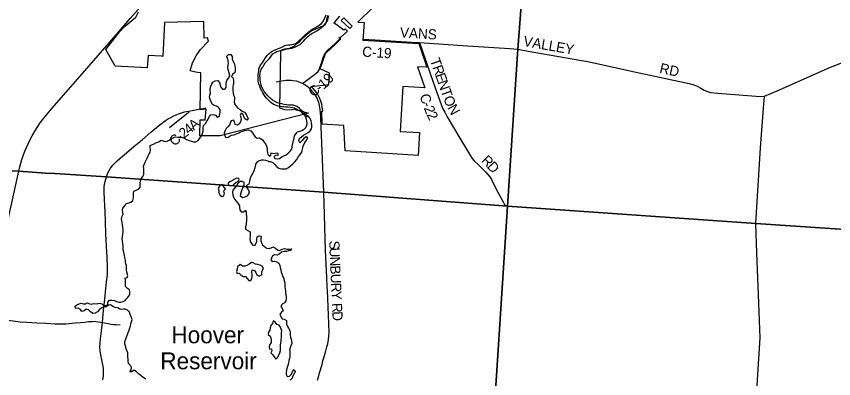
# Model space of a CAD drawing. Extents: x 1674899 to 2057726, y 653888 to 988278.
# Drawn here: x 1855438 to 1879677, y 798397 to 809139 of the extents above; entities that cross this region are included whole.
import ezdxf

# ---------------------------------------------------------------- set-up
doc = ezdxf.new("R2010")
doc.units = 0
for name, color, linetype in [('GM_X_Corporation', 7, 'Continuous'), ('GM_X_County_Road', 7, 'Continuous'), ('GM_X_County_Road_Text', 7, 'Continuous'), ('GM_X_Major_Lake', 7, 'Continuous'), ('GM_X_Major_Lake_Text', 7, 'Continuous'), ('GM_X_Major_River', 7, 'Continuous'), ('GM_X_State_Route', 7, 'Continuous'), ('GM_X_Township', 7, 'Continuous')]:
    doc.layers.add(name, color=color, linetype=linetype)

msp = doc.modelspace()

# ---------------------------------------------------------------- linework, layer by layer
at = {"layer": 'GM_X_Corporation'}
for points in [[(1866027, 809418), (1865570, 808968), (1865749, 808958), (1865718, 808434), (1867372, 808337), (1867616, 807629), (1867336, 807644), (1867551, 807021), (1866904, 807063), (1866822, 805729), (1867392, 805693), (1867351, 805018), (1866597, 805063), (1865185, 805154), (1865155, 805904), (1864509, 805942), (1864501, 806327), (1864526, 806328), (1864512, 806460), (1864496, 806536), (1864471, 806620), (1864437, 806705), (1864397, 806785), (1864365, 806841), (1864301, 806929), (1864242, 806997), (1864212, 807027), (1864179, 807057), (1864703, 807122), (1864724, 807458), (1864445, 807587), (1864609, 808041), (1864644, 808074), (1864880, 808299), (1865062, 808472), (1865032, 808472), (1865006, 808488), (1865043, 808523), (1865057, 808523), (1865255, 808704), (1865245, 808714), (1865194, 808766), (1865155, 808731), (1864852, 808948), (1864871, 808960), (1865028, 809140)], [(1864670, 809164), (1864633, 809031), (1864626, 808978), (1864590, 808873), (1864383, 808793), (1864180, 808703), (1864036, 808584), (1863894, 808456), (1863817, 808362), (1863732, 808311), (1863676, 808251), (1863563, 808196), (1863459, 808169), (1863269, 808119), (1863271, 808069), (1863240, 806424), (1863386, 806382), (1863526, 806367), (1863669, 806383), (1864106, 806273), (1861485, 805600), (1860876, 805597), (1860888, 806070), (1861038, 806073), (1861068, 806389), (1860885, 806368), (1860908, 807463), (1860893, 807463), (1860807, 807478), (1860713, 807490), (1860590, 807519), (1860665, 807762), (1860767, 807971), (1860900, 808159), (1861139, 808401), (1861111, 808506), (1861004, 808492), (1860999, 808987), (1859829, 808961), (1859781, 807951), (1859738, 807954), (1859344, 807980), (1859316, 807611), (1858367, 807661), (1858090, 808159), (1858507, 808685), (1858634, 808831), (1858740, 808916), (1858983, 809113), (1859065, 809276)]]:
    msp.add_lwpolyline(points, dxfattribs=at)
msp.add_lwpolyline([(1865072, 809017), (1865316, 808784), (1865324, 808776), (1865394, 808844), (1865384, 808855), (1865149, 809094)], close=True, dxfattribs=at)
at = {"layer": 'GM_X_County_Road'}
for points in [[(1863927, 807149), (1864283, 807418), (1864334, 807453), (1864387, 807502), (1864414, 807554), (1864439, 807622), (1864484, 807753), (1864542, 807914), (1864570, 807984), (1864606, 808050), (1864642, 808096), (1864687, 808146), (1864789, 808239), (1864902, 808347), (1864988, 808433), (1865037, 808477)], [(1865716, 808463), (1866076, 808441), (1867317, 808363), (1867396, 808359), (1868821, 808266), (1870074, 808188), (1870293, 808165)], [(1867396, 808359), (1867578, 807822), (1867722, 807411), (1867905, 806886), (1867988, 806661), (1868047, 806496), (1868091, 806398), (1868141, 806295), (1868218, 806162), (1868595, 805529), (1868820, 805149), (1868910, 805003), (1868961, 804924), (1869020, 804860), (1869146, 804736), (1869355, 804533), (1869481, 804376), (1869529, 804297), (1869678, 803996), (1869885, 803620), (1869914, 803562), (1869930, 803545)], [(1870293, 808165), (1870309, 808163), (1870615, 808110), (1872380, 807804), (1872796, 807716), (1873633, 807525), (1875394, 807147), (1875535, 807109), (1875625, 807069), (1875741, 807006), (1875837, 806950), (1875938, 806910), (1876028, 806878), (1876232, 806859), (1877504, 806767), (1877627, 806773), (1878001, 806934), (1879588, 807637), (1880629, 808038)], [(1863927, 807149), (1863854, 807181), (1863750, 807215), (1863635, 807231), (1863584, 807238), (1863480, 807241), (1863432, 807239), (1863243, 807210), (1863145, 807190)], [(1864561, 803891), (1864561, 803926), (1864503, 805153), (1864476, 805850), (1864464, 806156), (1864453, 806381), (1864432, 806497), (1864406, 806587), (1864383, 806653), (1864335, 806753), (1864289, 806830), (1864225, 806905), (1864168, 806969), (1864116, 807017), (1864089, 807036), (1863994, 807108), (1863927, 807149)], [(1877369, 802994), (1877508, 805242), (1877600, 806419), (1877627, 806773)], [(1858107, 804378), (1858154, 804496), (1858234, 804633), (1858313, 804738), (1858376, 804801), (1858430, 804854), (1858924, 805276), (1859165, 805478), (1859431, 805702), (1859655, 805890), (1859866, 806052), (1859951, 806106), (1860001, 806134), (1860128, 806199), (1860275, 806259), (1860424, 806303), (1860542, 806330), (1860650, 806352), (1860797, 806382), (1860914, 806399), (1861033, 806421), (1861065, 806429)], [(1860542, 806330), (1860547, 806309), (1860546, 806295), (1860544, 806288), (1860541, 806283), (1860532, 806274), (1860517, 806262), (1860480, 806237), (1860436, 806200), (1859981, 805831)], [(1858004, 798364), (1858012, 798409), (1858022, 798500), (1858025, 798592), (1858022, 798657), (1858018, 798708), (1858012, 798758), (1857995, 798858), (1857972, 798957), (1857933, 799154), (1857922, 799227), (1857914, 799334), (1857933, 799575), (1857961, 799815), (1857988, 800064), (1858027, 800427), (1858061, 800749), (1858095, 801069), (1858116, 801266), (1858139, 801481), (1858144, 801679), (1858131, 802013), (1858124, 802154), (1858116, 802308), (1858103, 802533), (1858096, 802669), (1858083, 803067), (1858070, 803343), (1858061, 803513), (1858050, 803726), (1858044, 803915), (1858041, 804015), (1858044, 804087), (1858051, 804150), (1858068, 804244), (1858087, 804316), (1858107, 804378)], [(1864372, 798348), (1864397, 798443), (1864431, 798566), (1864503, 798820), (1864532, 798925), (1864588, 799118), (1864615, 799218), (1864650, 799343), (1864671, 799432), (1864694, 799556), (1864707, 799664), (1864713, 799761), (1864693, 800283), (1864667, 801023), (1864657, 801114), (1864648, 801383), (1864604, 802208), (1864568, 803602), (1864561, 803891)], [(1869930, 803545), (1869936, 803538), (1870008, 803514), (1877369, 802994)], [(1877332, 796811), (1877420, 798367), (1877499, 799608), (1877454, 800633), (1877398, 802125), (1877369, 802994)], [(1854573, 800349), (1854755, 800266), (1854914, 800205), (1855015, 800169), (1855118, 800145), (1855340, 800109), (1855555, 800083), (1855746, 800073), (1856041, 800054), (1856308, 800043), (1856579, 800027), (1856677, 800021), (1856906, 800027), (1857196, 800056), (1857340, 800059), (1857473, 800073), (1857580, 800087), (1857682, 800095), (1857756, 800098), (1857798, 800096), (1857874, 800083), (1857988, 800064)], [(1857988, 800064), (1858110, 800041), (1858246, 800011), (1858305, 800003), (1858385, 799998), (1858516, 799994)]]:
    msp.add_lwpolyline(points, dxfattribs=at)
at = {"layer": 'GM_X_Major_Lake'}
for p, q in [((1861667, 807947), (1861729, 808005)), ((1864085, 806183), (1864016, 806160))]:
    msp.add_line(p, q, dxfattribs=at)
for points in [[(1861394, 806151), (1861456, 806166), (1861472, 806236), (1861479, 806305), (1861479, 806373), (1861438, 806435), (1861372, 806473), (1861308, 806498), (1861247, 806540), (1861217, 806608), (1861185, 806678), (1861164, 806743), (1861174, 806805), (1861191, 806863), (1861187, 806937), (1861185, 806999), (1861208, 807073), (1861238, 807137), (1861270, 807189), (1861339, 807226), (1861409, 807234), (1861460, 807173), (1861478, 807105), (1861501, 807035), (1861555, 806983), (1861621, 806978), (1861659, 807032), (1861658, 807098), (1861662, 807170), (1861680, 807238), (1861727, 807306), (1861769, 807372), (1861763, 807422), (1861740, 807490), (1861722, 807558), (1861711, 807625), (1861721, 807687), (1861725, 807737), (1861724, 807809), (1861712, 807879), (1861667, 807947)], [(1861729, 808005), (1861801, 808003), (1861837, 807952), (1861842, 807884), (1861860, 807818), (1861901, 807746), (1861921, 807676), (1861932, 807605), (1861932, 807539), (1861916, 807473), (1861853, 807416), (1861815, 807356), (1861865, 807305), (1861880, 807231), (1861876, 807161), (1861867, 807111), (1861857, 807049), (1861863, 806983), (1861862, 806933), (1861868, 806871), (1861881, 806803), (1861911, 806741), (1861905, 806679), (1861900, 806611), (1861910, 806544), (1861961, 806478), (1862005, 806412), (1862071, 806373), (1862132, 806323), (1862200, 806301), (1862250, 806240), (1862279, 806174), (1862313, 806110), (1862274, 806056), (1862217, 806102), (1862187, 806167), (1862168, 806229), (1862108, 806273), (1862072, 806211), (1862099, 806149), (1862105, 806083), (1862090, 806013), (1862050, 805947), (1861996, 805911), (1861930, 805930), (1861916, 805996), (1861875, 806060), (1861805, 806046), (1861781, 805987), (1861766, 805933), (1861714, 805865), (1861662, 805809), (1861623, 805739), (1861599, 805677), (1861614, 805613), (1861654, 805549), (1861724, 805560), (1861776, 805596), (1861826, 805616), (1861892, 805626), (1861964, 805653), (1862036, 805689), (1862088, 805711), (1862153, 805732), (1862211, 805754), (1862261, 805768), (1862327, 805779), (1862394, 805747), (1862442, 805685), (1862476, 805635), (1862523, 805568), (1862577, 805528), (1862653, 805535), (1862724, 805491), (1862782, 805423), (1862824, 805362), (1862857, 805290), (1862879, 805224), (1862880, 805156), (1862884, 805106), (1862901, 805042), (1862955, 804985)], [(1858739, 801474), (1858730, 801499), (1858716, 801559), (1858709, 801629), (1858707, 801681), (1858702, 801745), (1858684, 801805), (1858676, 801861), (1858671, 801913), (1858659, 801988), (1858648, 802046), (1858634, 802098), (1858624, 802148), (1858609, 802212), (1858603, 802280), (1858609, 802334), (1858596, 802406), (1858590, 802476), (1858581, 802544), (1858583, 802611), (1858592, 802681), (1858602, 802741), (1858602, 802811), (1858593, 802885), (1858583, 802953), (1858576, 803013), (1858566, 803083), (1858552, 803133), (1858571, 803199), (1858601, 803271), (1858600, 803321), (1858586, 803387), (1858598, 803455), (1858651, 803525), (1858695, 803591), (1858769, 803610), (1858833, 803634), (1858895, 803682), (1858916, 803754), (1858914, 803820), (1858917, 803888), (1858919, 803952), (1858991, 803986), (1859063, 804013), (1859110, 804077), (1859114, 804139), (1859114, 804205), (1859121, 804265), (1859135, 804331), (1859190, 804387), (1859222, 804453), (1859218, 804523), (1859215, 804577), (1859217, 804627), (1859213, 804699), (1859230, 804751), (1859260, 804811), (1859284, 804871), (1859315, 804939), (1859351, 805005), (1859375, 805058), (1859406, 805112), (1859420, 805174), (1859407, 805255), (1859407, 805307), (1859475, 805344), (1859527, 805364), (1859593, 805394), (1859661, 805423), (1859730, 805463), (1859795, 805447), (1859847, 805430), (1859909, 805436), (1859969, 805464), (1860040, 805517), (1860106, 805549), (1860156, 805563), (1860224, 805560), (1860290, 805554), (1860357, 805550), (1860425, 805525), (1860489, 805489), (1860561, 805461), (1860630, 805442), (1860690, 805422), (1860760, 805421), (1860826, 805461), (1860883, 805529), (1860931, 805595), (1860957, 805661), (1860978, 805733), (1860979, 805839), (1860989, 805907), (1861049, 805960), (1861086, 806030), (1861122, 806094), (1861160, 806162), (1861205, 806218), (1861279, 806232), (1861346, 806207), (1861394, 806151)], [(1863754, 804891), (1863763, 804919), (1863801, 804987), (1863854, 805045), (1863902, 805112), (1863912, 805162), (1863933, 805243), (1863945, 805293), (1863971, 805361), (1864000, 805413), (1864040, 805466), (1864080, 805540), (1864029, 805567), (1863962, 805519), (1863900, 805453), (1863848, 805385), (1863812, 805450), (1863840, 805516), (1863897, 805569), (1863953, 805613), (1864023, 805651), (1864093, 805693), (1864152, 805748), (1864188, 805800), (1864204, 805852), (1864205, 805914), (1864189, 805979), (1864181, 806043), (1864154, 806111), (1864100, 806172), (1864085, 806183)], [(1864016, 806160), (1864030, 806092), (1864041, 806042), (1864051, 805972), (1864045, 805903), (1864026, 805841), (1863958, 805776), (1863908, 805748), (1863840, 805726), (1863769, 805701)], [(1862955, 804985), (1862983, 805019), (1862998, 805091), (1863065, 805071), (1863117, 805079), (1863183, 805088), (1863201, 805026), (1863133, 805012), (1863073, 804979), (1863105, 804926), (1863172, 804916), (1863242, 804924), (1863309, 804977), (1863375, 804999), (1863437, 805037), (1863501, 805078), (1863559, 805138), (1863604, 805202), (1863618, 805268), (1863624, 805336), (1863643, 805406), (1863661, 805470), (1863676, 805532), (1863686, 805594), (1863769, 805701)], [(1862904, 804845), (1862838, 804868), (1862769, 804876), (1862705, 804877), (1862635, 804859), (1862578, 804821), (1862528, 804759), (1862518, 804689), (1862503, 804619), (1862479, 804553), (1862443, 804482), (1862412, 804428), (1862378, 804362), (1862364, 804308), (1862353, 804238), (1862331, 804162), (1862265, 804126), (1862262, 804066), (1862314, 804006), (1862339, 803932), (1862327, 803864), (1862269, 803808), (1862212, 803778), (1862148, 803760), (1862087, 803809), (1862093, 803877), (1862116, 803943), (1862136, 804009), (1862166, 804075), (1862195, 804141), (1862199, 804211), (1862135, 804239), (1862069, 804239), (1862011, 804180), (1861965, 804110), (1861910, 804048), (1861862, 803982), (1861848, 803914), (1861861, 803846), (1861875, 803782), (1861910, 803722), (1861962, 803663), (1862010, 803599), (1862053, 803525), (1862055, 803473), (1862068, 803407), (1862102, 803340), (1862170, 803348), (1862230, 803390), (1862254, 803329), (1862255, 803261), (1862259, 803211), (1862262, 803141), (1862262, 803091), (1862258, 803015), (1862251, 802961), (1862235, 802897), (1862234, 802825), (1862304, 802793), (1862368, 802752), (1862373, 802686), (1862373, 802608), (1862367, 802548), (1862374, 802488), (1862390, 802434), (1862439, 802368), (1862507, 802341), (1862552, 802411), (1862570, 802463), (1862570, 802525), (1862583, 802597), (1862639, 802633), (1862701, 802618), (1862692, 802550), (1862692, 802484), (1862707, 802424), (1862737, 802362), (1862803, 802310), (1862866, 802267), (1862940, 802257), (1862992, 802277), (1863060, 802304), (1863126, 802268), (1863182, 802220), (1863247, 802193), (1863320, 802235), (1863388, 802260), (1863459, 802234), (1863531, 802238), (1863599, 802251), (1863575, 802197), (1863505, 802188), (1863441, 802164), (1863371, 802171), (1863301, 802149), (1863237, 802091), (1863171, 802057), (1863095, 802066), (1863033, 802038), (1863002, 801974), (1862986, 801918)], [(1862904, 804845), (1862916, 804835), (1862980, 804831), (1863048, 804803), (1863105, 804744), (1863161, 804680), (1863225, 804638), (1863300, 804621), (1863368, 804615), (1863438, 804622), (1863508, 804660), (1863573, 804702), (1863641, 804765), (1863697, 804827), (1863754, 804891)], [(1862034, 804336), (1861968, 804344), (1861902, 804300), (1861838, 804259), (1861768, 804231), (1861716, 804195), (1861731, 804133), (1861803, 804127), (1861871, 804134)], [(1861871, 804134), (1861883, 804156), (1861949, 804212), (1862016, 804244), (1862046, 804308), (1862034, 804336)], [(1861544, 804151), (1861463, 804104), (1861427, 804045), (1861442, 803976), (1861444, 803908), (1861474, 803844), (1861535, 803802), (1861595, 803821), (1861608, 803893)], [(1861608, 803893), (1861603, 803909), (1861590, 803962), (1861639, 804017), (1861597, 804074), (1861544, 804151)], [(1862986, 801918), (1863028, 801868), (1863098, 801878), (1863165, 801861), (1863223, 801817), (1863249, 801751), (1863264, 801693), (1863282, 801621), (1863295, 801552), (1863317, 801484), (1863342, 801418), (1863366, 801364), (1863384, 801302), (1863401, 801238), (1863405, 801170), (1863404, 801118), (1863410, 801063), (1863416, 801001), (1863425, 800947), (1863433, 800883), (1863443, 800817), (1863442, 800767), (1863426, 800701), (1863386, 800645), (1863321, 800606), (1863281, 800538), (1863320, 800474), (1863350, 800411), (1863298, 800370), (1863257, 800302), (1863285, 800238), (1863319, 800173), (1863382, 800159), (1863446, 800123), (1863452, 800059), (1863453, 800008), (1863479, 799940), (1863513, 799890), (1863552, 799826), (1863558, 799760), (1863561, 799688), (1863571, 799622), (1863586, 799570), (1863602, 799507), (1863604, 799439), (1863583, 799369), (1863561, 799311), (1863540, 799246), (1863544, 799190), (1863552, 799123), (1863551, 799057), (1863539, 798991), (1863522, 798933), (1863510, 798858), (1863490, 798790), (1863467, 798726), (1863451, 798658), (1863436, 798582), (1863440, 798520), (1863472, 798460), (1863536, 798475), (1863600, 798535), (1863632, 798607), (1863675, 798667), (1863706, 798600), (1863672, 798534), (1863631, 798465), (1863615, 798411), (1863559, 798349)], [(1862080, 801781), (1861994, 801710), (1861985, 801643), (1861969, 801574), (1861985, 801519), (1862049, 801523), (1862094, 801473), (1862166, 801430), (1862234, 801428), (1862279, 801366), (1862329, 801305), (1862393, 801307), (1862425, 801375), (1862432, 801429), (1862428, 801491), (1862422, 801555), (1862433, 801619), (1862497, 801601), (1862542, 801544), (1862574, 801480), (1862639, 801434), (1862711, 801471)], [(1862711, 801471), (1862716, 801479), (1862722, 801553), (1862740, 801609), (1862771, 801663), (1862731, 801730), (1862667, 801762), (1862598, 801780), (1862530, 801795), (1862464, 801831), (1862410, 801837), (1862340, 801788), (1862278, 801748), (1862212, 801732), (1862146, 801731), (1862080, 801781)], [(1858344, 800714), (1858407, 800684), (1858473, 800664), (1858539, 800669), (1858601, 800689), (1858669, 800717), (1858718, 800778), (1858770, 800842), (1858808, 800914), (1858807, 800974), (1858797, 801034), (1858733, 801071), (1858678, 801125), (1858679, 801305), (1858669, 801373), (1858723, 801399), (1858744, 801455), (1858739, 801474)], [(1859274, 798384), (1859200, 798430), (1859131, 798487), (1859057, 798541), (1858999, 798600), (1858932, 798646), (1858866, 798604), (1858802, 798595), (1858844, 798654), (1858852, 798726), (1858823, 798791), (1858763, 798843), (1858756, 798911), (1858756, 798979), (1858749, 799045), (1858749, 799095), (1858741, 799159), (1858710, 799227), (1858692, 799294), (1858671, 799362), (1858655, 799426), (1858655, 799498), (1858684, 799576), (1858708, 799628), (1858735, 799704), (1858751, 799762), (1858780, 799837), (1858804, 799903), (1858820, 799955), (1858837, 800029), (1858857, 800081), (1858873, 800147), (1858844, 800227), (1858814, 800298), (1858797, 800364), (1858737, 800424), (1858670, 800458), (1858618, 800459), (1858564, 800447), (1858510, 800453), (1858446, 800496), (1858370, 800504), (1858296, 800536), (1858235, 800589), (1858169, 800571), (1858105, 800530), (1858037, 800512), (1857971, 800492), (1857906, 800447), (1857840, 800379), (1857776, 800337), (1857710, 800332), (1857640, 800380), (1857579, 800434), (1857511, 800459), (1857449, 800409), (1857383, 800385), (1857337, 800452), (1857271, 800490), (1857203, 800476), (1857174, 800541), (1857232, 800584), (1857300, 800612), (1857360, 800636), (1857426, 800617), (1857492, 800615), (1857542, 800641), (1857616, 800612), (1857668, 800604), (1857736, 800624), (1857805, 800615), (1857857, 800621), (1857911, 800633), (1857975, 800618), (1858025, 800566), (1858093, 800566), (1858147, 800595), (1858153, 800663), (1858200, 800727), (1858278, 800729), (1858344, 800714)], [(1863056, 800107), (1863034, 800037), (1862988, 799971), (1862961, 799903), (1862955, 799837), (1862917, 799775), (1862904, 799707), (1862962, 799653), (1862987, 799603), (1862991, 799539), (1862999, 799471), (1862960, 799407), (1862934, 799337), (1862941, 799273), (1863005, 799282), (1863011, 799218), (1862981, 799167), (1863048, 799106), (1863080, 799040), (1863129, 798976), (1863179, 799025), (1863222, 799091), (1863252, 799161), (1863271, 799231)], [(1863271, 799231), (1863269, 799251), (1863273, 799315), (1863274, 799387), (1863280, 799459), (1863288, 799511), (1863291, 799561), (1863299, 799619), (1863302, 799687), (1863306, 799755), (1863308, 799819), (1863295, 799869), (1863275, 799921), (1863233, 799982), (1863168, 800000), (1863122, 800066), (1863056, 800107)]]:
    msp.add_lwpolyline(points, dxfattribs=at)
at = {"layer": 'GM_X_Major_River'}
msp.add_line((1864016, 806160), (1864085, 806183), dxfattribs=at)
for points in [[(1863783, 808384), (1863837, 808432), (1863894, 808484), (1863954, 808544), (1864022, 808610), (1864099, 808670), (1864169, 808729), (1864235, 808769), (1864306, 808809), (1864368, 808846), (1864418, 808876), (1864486, 808926), (1864527, 808978), (1864563, 809044), (1864597, 809114), (1864622, 809180)], [(1863805, 808281), (1863851, 808306), (1863911, 808366), (1863963, 808410), (1864004, 808464), (1864068, 808531), (1864142, 808591), (1864205, 808631), (1864285, 808672), (1864351, 808710), (1864423, 808754), (1864482, 808798), (1864546, 808855), (1864608, 808923), (1864653, 808983), (1864671, 809033), (1864689, 809093), (1864706, 809167)], [(1863777, 806370), (1863751, 806386), (1863686, 806419), (1863632, 806427), (1863558, 806439), (1863490, 806448), (1863420, 806450), (1863368, 806453), (1863304, 806457), (1863248, 806467), (1863178, 806488), (1863126, 806508), (1863054, 806539), (1862984, 806585), (1862923, 806646), (1862861, 806712), (1862817, 806763), (1862776, 806817), (1862752, 806867), (1862716, 806931), (1862681, 807000), (1862655, 807066), (1862634, 807136), (1862612, 807219), (1862605, 807289), (1862609, 807339), (1862613, 807411), (1862618, 807461), (1862626, 807527), (1862634, 807585), (1862661, 807654), (1862693, 807705), (1862745, 807777), (1862780, 807829), (1862830, 807905), (1862879, 807975), (1862929, 808029), (1862995, 808089), (1863045, 808112), (1863112, 808146), (1863180, 808172), (1863244, 808199), (1863308, 808229), (1863376, 808265), (1863442, 808284), (1863494, 808296), (1863554, 808294), (1863605, 808304), (1863665, 808313), (1863733, 808345), (1863783, 808384)], [(1863845, 806388), (1863834, 806404), (1863764, 806462), (1863710, 806489), (1863658, 806501), (1863586, 806509), (1863514, 806508), (1863446, 806514), (1863384, 806521), (1863316, 806543), (1863256, 806553), (1863184, 806576), (1863037, 806653), (1862963, 806714), (1862894, 806780), (1862844, 806837), (1862792, 806907), (1862753, 806969), (1862721, 807042), (1862699, 807108), (1862678, 807186), (1862668, 807253), (1862665, 807307), (1862663, 807379), (1862669, 807449), (1862680, 807499), (1862702, 807569), (1862745, 807637), (1862775, 807695), (1862817, 807763), (1862946, 807886), (1862996, 807954), (1863049, 808024), (1863115, 808068), (1863165, 808092), (1863229, 808115), (1863280, 808129), (1863336, 808153), (1863404, 808176), (1863470, 808186), (1863540, 808186), (1863608, 808197), (1863670, 808217), (1863738, 808249), (1863805, 808281)], [(1863777, 806370), (1863841, 806344), (1863909, 806293), (1863972, 806229), (1864016, 806160)], [(1864085, 806183), (1864036, 806220), (1863969, 806289), (1863907, 806341), (1863845, 806388)]]:
    msp.add_lwpolyline(points, dxfattribs=at)
at = {"layer": 'GM_X_State_Route'}
msp.add_lwpolyline([(1853225, 794338), (1854573, 800349), (1855512, 804546), (1855541, 804679), (1855596, 804898), (1855689, 805139), (1855836, 805465), (1855908, 805599), (1856008, 805767), (1856148, 805978), (1856255, 806119), (1856504, 806413), (1857597, 807668), (1858467, 808668), (1858818, 809072), (1859440, 809788), (1860025, 810459)], dxfattribs=at)
at = {"layer": 'GM_X_Township'}
for points in [[(1870779, 814239), (1870309, 808163), (1870008, 803514), (1864561, 803926), (1858107, 804378), (1856579, 804475), (1856300, 804491), (1856177, 804502), (1855904, 804520), (1855512, 804546), (1855314, 804559)], [(1897406, 810815), (1897032, 804371), (1897004, 803896), (1896867, 801714), (1892288, 802025), (1891297, 802083), (1891221, 802088), (1891165, 802089), (1883392, 802588), (1877369, 802994), (1870008, 803514), (1870309, 808163), (1870779, 814239)], [(1855314, 804559), (1855512, 804546), (1855904, 804520), (1856177, 804502), (1856300, 804491), (1856579, 804475), (1858107, 804378), (1864561, 803926), (1870008, 803514), (1869596, 797271), (1869163, 789806), (1869111, 789007), (1869039, 787768), (1869000, 787580), (1869008, 787459), (1868914, 786029), (1868892, 785569), (1868890, 785515), (1868806, 784389), (1868751, 783613), (1868734, 783178), (1868439, 777975)], [(1881788, 775208), (1878568, 775400), (1872453, 775754), (1872401, 775756), (1868321, 776001), (1868439, 777975), (1868734, 783178), (1868751, 783613), (1868806, 784389), (1868890, 785515), (1868892, 785569), (1868914, 786029), (1869008, 787459), (1869000, 787580), (1869039, 787768), (1869111, 789007), (1869163, 789806), (1869596, 797271), (1870008, 803514), (1877369, 802994), (1883392, 802588)]]:
    msp.add_lwpolyline(points, dxfattribs=at)

# ---------------------------------------------------------------- texts
at = {"layer": 'GM_X_County_Road_Text'}
for s, rotation, p in [('VANS', 356.486, (1866809, 808516)), ('VALLEY', 349.9735, (1870459, 808263)), ('C-19', 356.2309, (1865688, 807948)), ('T', 289.2332, (1867701, 807844)), ('R', 289.233, (1867775, 807633)), ('RD', 347.6323, (1874495, 807466)), ('9', 52.222, (1864743, 807129)), ('E', 289.2332, (1867856, 807400)), ('1', 38.2215, (1864542, 806958)), ('N', 289.2321, (1867930, 807188)), ('C', 36.8949, (1864240, 806731)), ('-', 37.0864, (1864438, 806880)), ('T', 289.2549, (1868017, 806939)), ('C', 288.5621, (1867392, 806787)), ('O', 290.7713, (1868094, 806719)), ('2', 291.3014, (1867518, 806423)), ('-', 290.0283, (1867474, 806545)), ('N', 299.1866, (1868208, 806428)), ('2', 296.202, (1867597, 806225)), ('A', 40.1226, (1860699, 805742)), ('2', 38.9442, (1860407, 805505)), ('4', 39.1303, (1860551, 805622)), ('C', 38.8725, (1860119, 805273)), ('-', 38.8756, (1860310, 805427)), ('R', 315.2318, (1869206, 804843)), ('D', 311.7192, (1869378, 804674)), ('S', 271.0739, (1864719, 802486)), ('U', 272.1003, (1864723, 802278)), ('N', 272.6287, (1864733, 802011)), ('B', 272.6533, (1864745, 801747)), ('U', 272.6492, (1864756, 801501)), ('R', 272.6513, (1864768, 801237)), ('Y', 272.6529, (1864780, 800991)), ('R', 272.6513, (1864796, 800635)), ('D', 272.6529, (1864808, 800389))]:
    msp.add_text(s, height=300, rotation=rotation, dxfattribs=at).set_placement(p)
at = {"layer": 'GM_X_Major_Lake_Text'}
for s, p in [('Hoover', (1860036, 799446)), ('Reservoir', (1859707, 798675))]:
    msp.add_text(s, height=500, rotation=0.0024, dxfattribs=at).set_placement(p)

doc.saveas('drawing.dxf')
